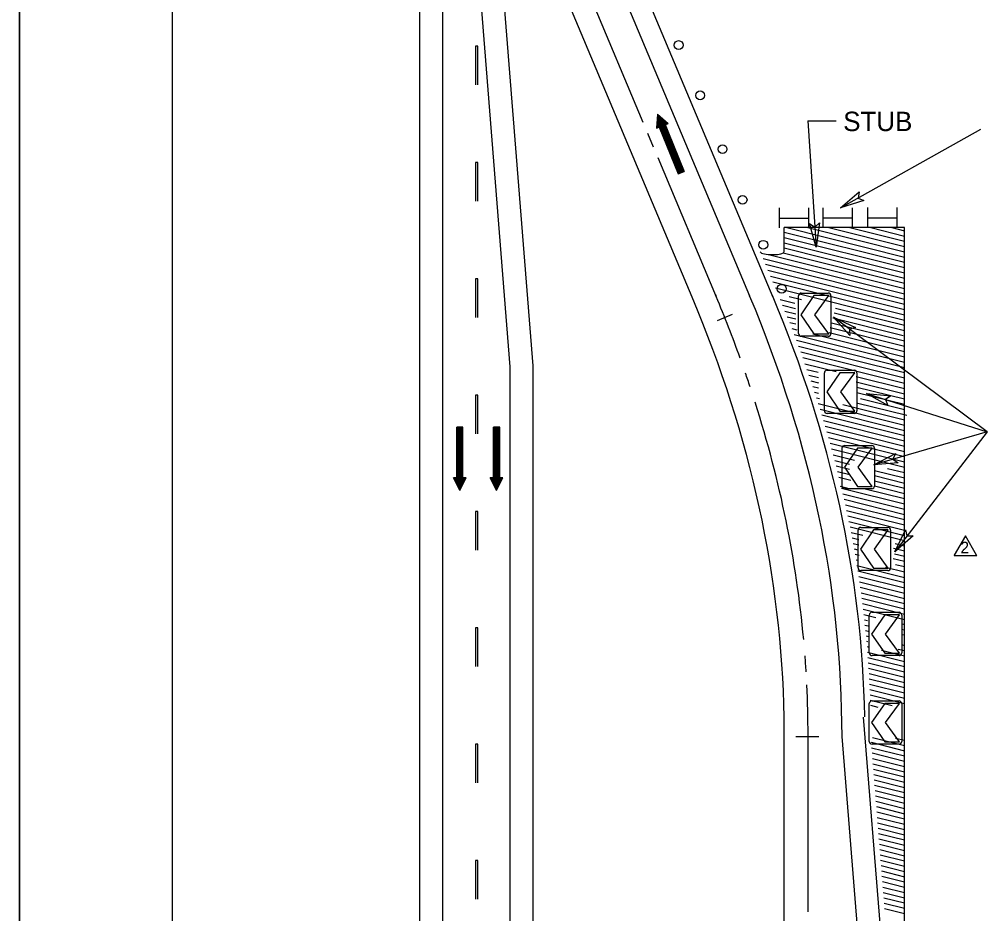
# Model space of a CAD drawing. Extents: x 1806 to 2022, y 110 to 389.
# Drawn here: x 1805.6 to 1926.6, y 180.5 to 292 of the extents above; entities that cross this region are included whole.
import ezdxf

# ---------------------------------------------------------------- set-up
doc = ezdxf.new("R2010")
doc.units = 0
for name, color, linetype in [('Level 1', 7, 'Continuous'), ('Level 10', 7, 'Continuous'), ('Level 2', 7, 'Continuous'), ('Level 3', 7, 'Continuous'), ('Level 44', 7, 'Continuous'), ('Level 60', 7, 'Continuous'), ('Level 63', 7, 'Continuous'), ('Level 7', 7, 'Continuous')]:
    doc.layers.add(name, color=color, linetype=linetype)

msp = doc.modelspace()

# ---------------------------------------------------------------- linework, layer by layer
at = {"layer": 'Level 1'}
msp.add_line((1892.57, 257.44), (1892.57, 257.44), dxfattribs=at)
at = {"layer": 'Level 10'}
for p, q in [((1885.24, 280.21), (1885.1, 278.45)), ((1885.18, 279.55), (1887.91, 272.79)), ((1885.2, 279.77), (1888.01, 272.83)), ((1885.22, 279.99), (1888.1, 272.87)), ((1885.24, 280.21), (1888.19, 272.9)), ((1885.24, 280.21), (1886.56, 279.05)), ((1885.4, 280.07), (1888.28, 272.94)), ((1885.57, 279.92), (1888.37, 272.98)), ((1885.73, 279.77), (1888.46, 273.01)), ((1885.9, 279.63), (1888.55, 273.05)), ((1886.06, 279.48), (1886.28, 278.93)), ((1885.1, 278.45), (1885.46, 278.6)), ((1885.11, 278.67), (1885.19, 278.49)), ((1885.13, 278.89), (1885.28, 278.53)), ((1885.15, 279.11), (1885.37, 278.56)), ((1885.16, 279.33), (1887.82, 272.75)), ((1885.46, 278.6), (1887.82, 272.75)), ((1886.19, 278.9), (1886.56, 279.05)), ((1886.19, 278.9), (1888.55, 273.05)), ((1886.23, 279.34), (1886.37, 278.97)), ((1886.39, 279.19), (1886.47, 279.01)), ((1887.82, 272.75), (1888.55, 273.05)), ((1900.46, 266.05), (1900.46, 268.52)), ((1904.13, 266.05), (1904.13, 268.52)), ((1905.91, 266.05), (1905.91, 268.52)), ((1909.59, 266.05), (1909.59, 268.52)), ((1911.48, 266.1), (1911.48, 268.57)), ((1915.15, 266.1), (1915.15, 268.57)), ((1900.46, 267.24), (1904.13, 267.24)), ((1905.86, 267.29), (1909.54, 267.29)), ((1911.43, 267.29), (1915.1, 267.29)), ((1903.19, 257.9), (1906.55, 257.9)), ((1902.84, 252.85), (1902.84, 257.56)), ((1904.77, 257.59), (1903.14, 255.19)), ((1906.61, 257.59), (1904.77, 257.59)), ((1904.87, 255.19), (1906.61, 257.59)), ((1906.89, 257.56), (1906.89, 252.85)), ((1903.14, 255.19), (1904.77, 252.8)), ((1906.61, 252.8), (1904.87, 255.19)), ((1906.55, 252.5), (1903.19, 252.5)), ((1904.77, 252.8), (1906.61, 252.8)), ((1906.42, 248.27), (1909.79, 248.27)), ((1906.08, 243.22), (1906.08, 247.93)), ((1908.01, 247.96), (1906.37, 245.56)), ((1909.85, 247.96), (1908.01, 247.96)), ((1908.11, 245.56), (1909.85, 247.96)), ((1910.13, 247.93), (1910.13, 243.22)), ((1906.37, 245.56), (1908.01, 243.17)), ((1909.85, 243.17), (1908.11, 245.56)), ((1911.31, 245.37), (1926.37, 240.6)), ((1909.79, 242.87), (1906.42, 242.87)), ((1908.01, 243.17), (1909.85, 243.17)), ((1860.17, 234.86), (1860.17, 241.17)), ((1860.96, 241.17), (1860.17, 241.17)), ((1860.17, 234.07), (1860.17, 241.17)), ((1860.27, 233.88), (1860.27, 241.17)), ((1860.37, 233.68), (1860.37, 241.17)), ((1860.47, 233.48), (1860.47, 241.17)), ((1860.57, 233.28), (1860.57, 241.17)), ((1860.66, 233.48), (1860.66, 241.17)), ((1860.76, 233.68), (1860.76, 241.17)), ((1860.86, 233.88), (1860.86, 241.17)), ((1860.96, 234.86), (1860.96, 241.17)), ((1860.96, 234.07), (1860.96, 241.17)), ((1864.76, 234.86), (1864.76, 241.17)), ((1865.54, 241.17), (1864.76, 241.17)), ((1864.76, 234.07), (1864.76, 241.17)), ((1864.85, 233.88), (1864.85, 241.17)), ((1864.95, 233.68), (1864.95, 241.17)), ((1865.05, 233.48), (1865.05, 241.17)), ((1865.15, 233.28), (1865.15, 241.17)), ((1865.25, 233.48), (1865.25, 241.17)), ((1865.35, 233.68), (1865.35, 241.17)), ((1865.45, 233.88), (1865.45, 241.17)), ((1865.54, 234.86), (1865.54, 241.17)), ((1865.54, 234.07), (1865.54, 241.17)), ((1926.37, 240.6), (1912.23, 236.45)), ((1908.27, 233.82), (1908.27, 238.54)), ((1910.19, 238.56), (1908.56, 236.17)), ((1908.61, 238.88), (1911.98, 238.88)), ((1912.04, 238.56), (1910.19, 238.56)), ((1910.3, 236.17), (1912.04, 238.56)), ((1912.32, 238.54), (1912.32, 233.82)), ((1908.56, 236.17), (1910.19, 233.77)), ((1912.04, 233.77), (1910.3, 236.17)), ((1860.57, 233.28), (1859.78, 234.86)), ((1860.17, 234.86), (1859.78, 234.86)), ((1859.88, 234.66), (1859.88, 234.86)), ((1859.97, 234.47), (1859.97, 234.86)), ((1860.07, 234.27), (1860.07, 234.86)), ((1860.57, 233.28), (1861.35, 234.86)), ((1861.35, 234.86), (1860.96, 234.86)), ((1861.06, 234.27), (1861.06, 234.86)), ((1861.16, 234.47), (1861.16, 234.86)), ((1861.26, 234.66), (1861.26, 234.86)), ((1865.15, 233.28), (1864.36, 234.86)), ((1864.76, 234.86), (1864.36, 234.86)), ((1864.46, 234.66), (1864.46, 234.86)), ((1864.56, 234.47), (1864.56, 234.86)), ((1864.66, 234.27), (1864.66, 234.86)), ((1865.15, 233.28), (1865.94, 234.86)), ((1865.94, 234.86), (1865.54, 234.86)), ((1865.64, 234.27), (1865.64, 234.86)), ((1865.74, 234.47), (1865.74, 234.86)), ((1865.84, 234.66), (1865.84, 234.86)), ((1910.19, 233.77), (1912.04, 233.77)), ((1911.98, 233.48), (1908.61, 233.48)), ((1910.62, 228.67), (1913.99, 228.67)), ((1910.28, 223.61), (1910.28, 228.32)), ((1912.21, 228.35), (1910.57, 225.95)), ((1914.05, 228.35), (1912.21, 228.35)), ((1912.31, 225.95), (1914.05, 228.35)), ((1914.33, 228.32), (1914.33, 223.61)), ((1910.57, 225.95), (1912.21, 223.56)), ((1914.05, 223.56), (1912.31, 225.95)), ((1913.99, 223.27), (1910.62, 223.27)), ((1912.21, 223.56), (1914.05, 223.56)), ((1912.02, 218.07), (1915.39, 218.07)), ((1911.68, 213.01), (1911.68, 217.73)), ((1913.61, 217.75), (1911.97, 215.36)), ((1915.45, 217.75), (1913.61, 217.75)), ((1913.71, 215.36), (1915.45, 217.75)), ((1915.73, 217.73), (1915.73, 213.01)), ((1911.97, 215.36), (1913.61, 212.97)), ((1915.45, 212.97), (1913.71, 215.36)), ((1913.61, 212.97), (1915.45, 212.97)), ((1915.39, 212.67), (1912.02, 212.67)), ((1912.02, 207.02), (1915.39, 207.02)), ((1911.68, 201.96), (1911.68, 206.68)), ((1913.61, 206.7), (1911.97, 204.31)), ((1915.45, 206.7), (1913.61, 206.7)), ((1913.71, 204.31), (1915.45, 206.7)), ((1915.73, 206.68), (1915.73, 201.96)), ((1911.97, 204.31), (1913.61, 201.92)), ((1915.45, 201.92), (1913.71, 204.31)), ((1915.39, 201.62), (1912.02, 201.62)), ((1913.61, 201.92), (1915.45, 201.92))]:
    msp.add_line(p, q, dxfattribs=at)
for points in [[(1911.31, 245.37), (1914.36, 245.06), (1913.7, 244.61), (1913.99, 243.87)], [(1912.23, 236.45), (1914.94, 237.89), (1914.63, 237.16), (1915.29, 236.7)]]:
    msp.add_lwpolyline(points, close=True, dxfattribs=at)
for centre, start, end in [((1903.19, 257.56), 90, 180), ((1906.55, 257.56), 360, 90), ((1903.19, 252.85), 180, 270), ((1906.55, 252.85), 270, 360), ((1906.42, 247.93), 90, 180), ((1909.79, 247.93), 360, 90), ((1906.42, 243.22), 180, 270), ((1909.79, 243.22), 270, 360), ((1908.61, 238.54), 90, 180), ((1911.98, 238.54), 360, 90), ((1908.61, 233.82), 180, 270), ((1911.98, 233.82), 270, 360), ((1910.62, 228.32), 90, 180), ((1913.99, 228.32), 360, 90), ((1910.62, 223.61), 180, 270), ((1913.99, 223.61), 270, 360), ((1912.02, 217.73), 90, 180), ((1915.39, 217.73), 360, 90), ((1912.02, 213.01), 180, 270), ((1915.39, 213.01), 270, 360), ((1912.02, 206.68), 90, 180), ((1915.39, 206.68), 360, 90), ((1912.02, 201.96), 180, 270), ((1915.39, 201.96), 270, 360)]:
    msp.add_arc(centre, 0.342, start, end, dxfattribs=at)
at = {"layer": 'Level 2'}
for p, q in [((1858.46, 138.73), (1858.46, 362.35)), ((1878.36, 301.3), (1896.74, 257.55)), ((1866.86, 248.69), (1862.66, 301.19)), ((1874.18, 301.19), (1883.41, 279.23)), ((1862.52, 288.71), (1862.52, 283.87)), ((1862.81, 288.71), (1862.52, 288.71)), ((1862.81, 283.87), (1862.81, 288.71)), ((1883.99, 277.86), (1884.71, 276.14)), ((1885.28, 274.79), (1892.57, 257.44)), ((1862.52, 274.19), (1862.52, 269.36)), ((1862.81, 274.19), (1862.52, 274.19)), ((1862.81, 269.36), (1862.81, 274.19)), ((1862.52, 259.68), (1862.52, 254.84)), ((1862.81, 259.68), (1862.52, 259.68)), ((1862.81, 254.84), (1862.81, 259.68)), ((1866.86, 138.73), (1866.86, 248.69)), ((1862.52, 245.17), (1862.52, 240.33)), ((1862.81, 245.17), (1862.52, 245.17)), ((1862.81, 240.33), (1862.81, 245.17)), ((1862.52, 230.65), (1862.52, 225.81)), ((1862.81, 230.65), (1862.52, 230.65)), ((1862.81, 225.81), (1862.81, 230.65)), ((1862.52, 216.14), (1862.52, 211.3)), ((1862.81, 216.14), (1862.52, 216.14)), ((1862.81, 211.3), (1862.81, 216.14)), ((1908.26, 202.57), (1910.51, 174.44)), ((1862.52, 201.62), (1862.52, 196.79)), ((1862.81, 201.62), (1862.52, 201.62)), ((1862.81, 196.79), (1862.81, 201.62)), ((1862.52, 187.11), (1862.52, 182.27)), ((1862.81, 187.11), (1862.52, 187.11)), ((1862.81, 182.27), (1862.81, 187.11))]:
    msp.add_line(p, q, dxfattribs=at)
for centre, major_axis, start_param, end_param in [((-189.78, 202.73), (2093.81, 0), 0.090033, 0.104721), ((-195.92, 202.56), (2104.19, 0), 0, 0.104721), ((-189.78, 202.73), (2093.81, 0), 0.08316, 0.086443), ((-189.78, 202.73), (2093.81, 0), 0.022808, 0.079434), ((-189.78, 202.73), (2093.81, 0), 0.015122, 0.018918), ((-189.78, 202.73), (2093.81, 0), 0, 0.011993)]:
    msp.add_ellipse(centre, major_axis=major_axis, ratio=0.25, start_param=start_param, end_param=end_param, dxfattribs=at)
at = {"layer": 'Level 3'}
for p, q in [((1901.06, 265.49), (1916.06, 261.74)), ((1901.37, 266.06), (1916.06, 262.39)), ((1903.99, 266.06), (1916.06, 263.05)), ((1906.61, 266.06), (1916.06, 263.7)), ((1909.24, 266.06), (1916.06, 264.36)), ((1911.85, 266.06), (1916.06, 265.01)), ((1914.47, 266.06), (1916.06, 265.67)), ((1901.06, 264.83), (1916.06, 261.08)), ((1901.06, 264.18), (1916.06, 260.43)), ((1899.08, 262.71), (1916.06, 258.46)), ((1900.92, 262.9), (1916.06, 259.12)), ((1901.06, 263.52), (1916.06, 259.77)), ((1898.41, 262.22), (1916.06, 257.81)), ((1898.72, 261.49), (1916.06, 257.15)), ((1899.03, 260.75), (1916.06, 256.5)), ((1899.34, 260.02), (1916.06, 255.84)), ((1899.64, 259.29), (1916.06, 255.19)), ((1899.95, 258.56), (1916.06, 254.53)), ((1900.55, 257.1), (1902.37, 256.64)), ((1901.69, 257.47), (1903.21, 257.09)), ((1900.85, 256.37), (1902.45, 255.97)), ((1901.15, 255.65), (1902.49, 255.31)), ((1907.27, 255.42), (1916.06, 253.22)), ((1907.47, 256.02), (1916.06, 253.88)), ((1901.44, 254.93), (1902.51, 254.66)), ((1902.5, 254.01), (1901.76, 254.2)), ((1906.96, 254.19), (1916.06, 251.92)), ((1907.12, 254.81), (1915.9, 252.61)), ((1902.02, 253.46), (1902.62, 253.31)), ((1906.66, 252.97), (1916.06, 250.62)), ((1906.81, 253.58), (1916.06, 251.27)), ((1902.29, 252.73), (1916.06, 249.29)), ((1902.57, 252.01), (1916.06, 248.63)), ((1904.61, 252.81), (1916.06, 249.94)), ((1902.84, 251.28), (1916.06, 247.98)), ((1903.11, 250.56), (1916.06, 247.32)), ((1903.37, 249.84), (1916.06, 246.67)), ((1903.64, 249.08), (1907.53, 248.11)), ((1903.89, 248.37), (1905.28, 248.02)), ((1904.14, 247.66), (1905.33, 247.36)), ((1904.38, 246.94), (1905.32, 246.71)), ((1910.03, 246.83), (1916.06, 245.33)), ((1910.05, 247.47), (1916.06, 245.97)), ((1904.62, 246.24), (1905.32, 246.06)), ((1910.14, 246.15), (1916.06, 244.68)), ((1904.85, 245.53), (1905.32, 245.41)), ((1905.08, 244.82), (1905.44, 244.73)), ((1910.13, 245.51), (1916.06, 244.03)), ((1910.59, 244.74), (1916.06, 243.38)), ((1905.31, 244.12), (1916.06, 241.43)), ((1905.53, 243.41), (1916.06, 240.77)), ((1908.37, 244), (1916.06, 242.08)), ((1910.07, 244.22), (1916.36, 242.65)), ((1905.75, 242.7), (1916.06, 240.12)), ((1905.96, 241.99), (1916.06, 239.46)), ((1906.17, 241.28), (1916.06, 238.81)), ((1906.38, 240.57), (1916.06, 238.15)), ((1906.58, 239.87), (1916.06, 237.5)), ((1906.78, 239.16), (1916.06, 236.84)), ((1906.97, 238.46), (1916.06, 236.19)), ((1907.17, 237.72), (1909.81, 237.06)), ((1907.36, 237.02), (1909.22, 236.56)), ((1907.54, 236.33), (1909.19, 235.92)), ((1913.94, 236.03), (1916.06, 235.5)), ((1907.71, 235.64), (1909.24, 235.25)), ((1907.89, 234.94), (1909.37, 234.57)), ((1912.32, 235.78), (1916.06, 234.85)), ((1912.32, 235.13), (1916.06, 234.2)), ((1908.06, 233.79), (1909.27, 233.48)), ((1908.22, 233.56), (1909.07, 233.35)), ((1912.32, 234.48), (1916.06, 233.55)), ((1912.32, 233.84), (1916.06, 232.9)), ((1908.38, 232.87), (1916.06, 230.95)), ((1908.55, 233.48), (1916.06, 231.6)), ((1911.15, 233.48), (1916.06, 232.25)), ((1908.54, 232.17), (1916.06, 230.29)), ((1908.69, 231.48), (1916.06, 229.64)), ((1908.84, 230.79), (1916.06, 228.98)), ((1908.99, 230.09), (1916.06, 228.33)), ((1909.13, 229.4), (1916.06, 227.67)), ((1909.27, 228.72), (1915.9, 227.06)), ((1909.4, 228.04), (1910.85, 227.68)), ((1909.54, 227.36), (1910.37, 227.15)), ((1909.66, 226.67), (1910.36, 226.5)), ((1914.9, 226.66), (1916.06, 226.37)), ((1909.79, 225.99), (1910.26, 225.88)), ((1909.9, 225.31), (1910.43, 225.18)), ((1914.71, 226.06), (1916.06, 225.72)), ((1914.84, 225.38), (1916.06, 225.07)), ((1910.02, 224.63), (1910.32, 224.56)), ((1910.14, 223.91), (1916.06, 222.43)), ((1914.64, 224.78), (1916.06, 224.43)), ((1914.94, 224.05), (1916.06, 223.77)), ((1910.25, 223.23), (1916.06, 221.78)), ((1913.7, 223.72), (1916.06, 223.12)), ((1910.35, 222.55), (1916.06, 221.12)), ((1910.45, 221.87), (1916.06, 220.47)), ((1910.55, 221.19), (1916.06, 219.81)), ((1910.65, 220.51), (1916.06, 219.16)), ((1910.74, 219.83), (1916.06, 218.5)), ((1910.82, 219.16), (1916.06, 217.85)), ((1910.91, 218.48), (1916.06, 217.19)), ((1910.99, 217.81), (1912.48, 217.44)), ((1911.06, 217.14), (1911.47, 217.04)), ((1915.76, 216.62), (1916.06, 216.54)), ((1911.13, 216.47), (1911.55, 216.37)), ((1911.2, 215.81), (1911.52, 215.73)), ((1915.71, 215.98), (1916.06, 215.89)), ((1911.27, 215.14), (1911.59, 215.06)), ((1911.33, 214.48), (1911.46, 214.44)), ((1915.79, 215.31), (1916.06, 215.24)), ((1915.97, 214.62), (1916.06, 214.59)), ((1911.39, 213.81), (1911.53, 213.78)), ((1911.45, 213.1), (1916.06, 211.95)), ((1913.19, 213.36), (1916.06, 212.64)), ((1915.29, 213.49), (1916.06, 213.29)), ((1915.84, 214), (1916.06, 213.94)), ((1911.5, 212.44), (1916.06, 211.3)), ((1911.55, 211.77), (1916.06, 210.64)), ((1911.59, 211.1), (1916.06, 209.99)), ((1911.64, 210.44), (1916.06, 209.33)), ((1911.67, 209.77), (1916.06, 208.68)), ((1911.71, 209.11), (1916.06, 208.02)), ((1911.74, 208.45), (1916.06, 207.37)), ((1911.77, 207.78), (1916.06, 206.71)), ((1911.79, 207.13), (1914.54, 206.44)), ((1911.81, 206.47), (1912.74, 206.24)), ((1912.07, 202.46), (1916.06, 201.46)), ((1914.94, 202.39), (1916.06, 202.11)), ((1911.91, 201.85), (1916.06, 200.81)), ((1911.97, 201.18), (1916.06, 200.16)), ((1912.02, 200.52), (1916.06, 199.5)), ((1912.08, 199.85), (1916.06, 198.85)), ((1912.13, 199.18), (1916.06, 198.19)), ((1912.18, 198.51), (1916.06, 197.54)), ((1912.24, 197.84), (1916.06, 196.88)), ((1912.29, 197.17), (1916.06, 196.23)), ((1912.34, 196.5), (1916.06, 195.58)), ((1912.4, 195.84), (1916.06, 194.92)), ((1912.45, 195.17), (1916.06, 194.26)), ((1912.5, 194.5), (1916.06, 193.61)), ((1912.56, 193.83), (1916.06, 192.95)), ((1912.61, 193.16), (1916.06, 192.3)), ((1912.66, 192.49), (1916.06, 191.64)), ((1912.72, 191.82), (1916.06, 190.99)), ((1912.77, 191.16), (1916.06, 190.33)), ((1912.83, 190.49), (1916.06, 189.68)), ((1912.88, 189.82), (1916.06, 189.02)), ((1912.93, 189.15), (1916.06, 188.37)), ((1912.99, 188.48), (1916.06, 187.71)), ((1913.04, 187.81), (1916.06, 187.06)), ((1913.09, 187.15), (1916.06, 186.4)), ((1913.15, 186.48), (1916.06, 185.75)), ((1913.2, 185.81), (1916.06, 185.09)), ((1913.25, 185.14), (1916.06, 184.44)), ((1913.31, 184.47), (1916.06, 183.78)), ((1913.36, 183.8), (1916.06, 183.13)), ((1913.41, 183.13), (1916.06, 182.47)), ((1913.47, 182.47), (1916.06, 181.82)), ((1913.52, 181.8), (1916.06, 181.16)), ((1913.57, 181.13), (1916.06, 180.51))]:
    msp.add_line(p, q, dxfattribs=at)
for centre in [(1887.88, 288.83), (1890.56, 282.56), (1893.36, 275.85), (1895.86, 269.53), (1898.44, 263.92), (1900.74, 258.43)]:
    msp.add_circle(centre, 0.552, dxfattribs=at)
at = {"layer": 'Level 60'}
msp.add_line((1805.59, 389.18), (1805.59, 110.17), dxfattribs=at)
for points in [[(1805.59, 389.18), (2021.59, 389.18), (2021.59, 110.18), (1805.59, 110.18)], [(1824.71, 378.37), (2011.59, 378.37), (2011.59, 120.98), (1824.71, 120.98)]]:
    msp.add_lwpolyline(points, close=True, dxfattribs=at)
at = {"layer": 'Level 63'}
for points in [[(1923.68, 227.62), (1922.28, 225.19)], [(1925.07, 225.19), (1923.68, 227.62)], [(1922.28, 225.19), (1922.26, 225.15), (1925.1, 225.15), (1925.07, 225.19)]]:
    msp.add_lwpolyline(points, dxfattribs=at)
at = {"layer": 'Level 7'}
for p, q in [((1889.58, 257.38), (1868.41, 307.71)), ((1855.59, 246.06), (1855.59, 303.67)), ((1869.73, 248.81), (1865.53, 301.31)), ((1881.26, 301.11), (1899.65, 257.38)), ((1904, 279.39), (1907.53, 279.39)), ((1904, 279.39), (1905.04, 263.63)), ((1908.09, 268.51), (1925.6, 278.35)), ((1901.06, 263.06), (1901.06, 266.06)), ((1916.06, 266.06), (1901.06, 266.06)), ((1916.06, 233.68), (1916.06, 266.06)), ((1892.57, 257.44), (1892.57, 257.67)), ((1892.73, 254.47), (1894.61, 255.26)), ((1926.37, 240.6), (1907.19, 254.89)), ((1869.73, 138.73), (1869.73, 248.81)), ((1855.59, 146.16), (1855.59, 246.06)), ((1926.37, 240.6), (1914.85, 225.61)), ((1916.06, 146.33), (1916.06, 233.68)), ((1901.06, 138.73), (1901.06, 204.98)), ((1910.93, 204.98), (1915.33, 150.03)), ((1902.52, 202.56), (1905.38, 202.56)), ((1904.06, 180.7), (1904.06, 202.73))]:
    msp.add_line(p, q, dxfattribs=at)
for points in [[(1908.09, 268.51), (1910.4, 270.52), (1910.27, 269.74), (1911, 269.44)], [(1905.04, 263.63), (1904.22, 266.58), (1904.87, 266.13), (1905.46, 266.66)], [(1907.19, 254.89), (1909.97, 253.59), (1909.2, 253.39), (1909.23, 252.6)], [(1914.85, 225.61), (1916.19, 228.37), (1916.38, 227.6), (1917.17, 227.61)]]:
    msp.add_lwpolyline(points, close=True, dxfattribs=at)
for centre, major_axis, ratio, start_param, end_param in [((1899.56, 263.06), (1.5, 0), 0.25, 3.246312, 6.283185), ((-195.92, 202.56), (2096.99, 0), 0.25, 0.004607, 0.104755), ((-195.92, 202.56), (2107.06, 0), 0.24974, 0.004697, 0.104757)]:
    msp.add_ellipse(centre, major_axis=major_axis, ratio=ratio, start_param=start_param, end_param=end_param, dxfattribs=at)

# ---------------------------------------------------------------- texts
at = {"layer": 'Level 44'}
msp.add_text('2', height=1.45, rotation=360, dxfattribs=at).set_placement((1923.05, 225.42))
at = {"layer": 'Level 7'}
msp.add_text('STUB', height=2.419, dxfattribs=at).set_placement((1908.42, 278.1))

doc.saveas('drawing.dxf')
